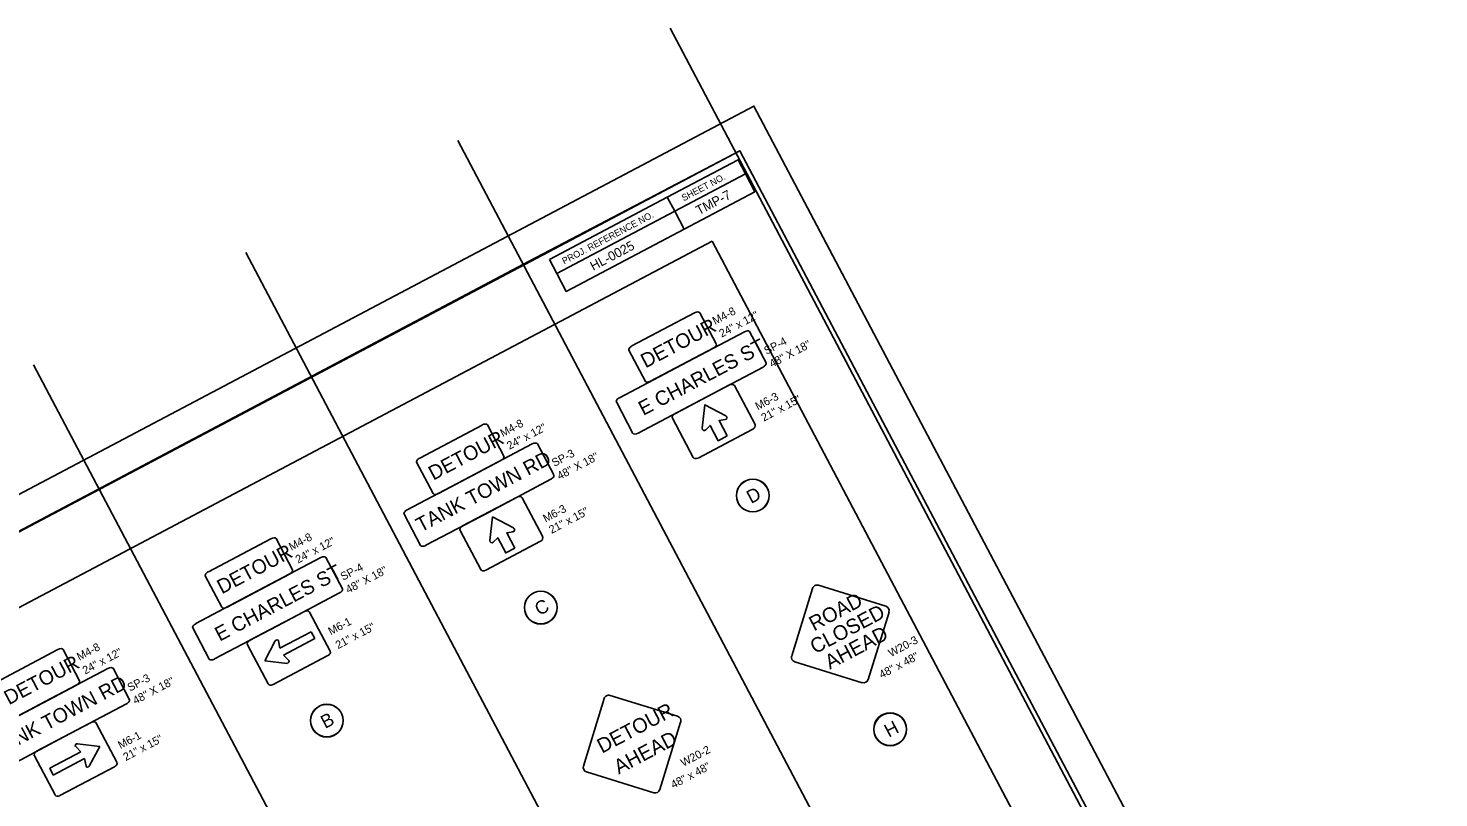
# Model space of a CAD drawing. Extents: x 1487176 to 2935813, y 497724 to 1002340.
# Drawn here: x 1488583 to 1489641, y 499179 to 499756 of the extents above; entities that cross this region are included whole.
import ezdxf

# ---------------------------------------------------------------- set-up
doc = ezdxf.new("R2010")
doc.units = 0
for name, color, linetype in [('DEV BORDER CELL', 7, 'Continuous'), ('Gray Area Fill Shapes', 7, 'Continuous'), ('GS M4-8 CELL', 7, 'Continuous'), ('Scratch_Level_0', 7, 'Continuous'), ('Scratch_Level_1', 7, 'Continuous'), ('Scratch_Level_3', 7, 'Continuous'), ('Sheet Plot Border Outside CELL', 7, 'Continuous'), ('WZ DETAHD CELL', 7, 'Continuous'), ('WZ OSDHWYEND CELL', 7, 'Continuous'), ('WZ OSDHWYL CELL', 7, 'Continuous'), ('WZ OSDHWYR CELL', 7, 'Continuous'), ('WZ OSDHWYS CELL', 7, 'Continuous'), ('WZ OSDR CELL', 7, 'Continuous'), ('WZ RCA CELL', 7, 'Continuous')]:
    doc.layers.add(name, color=color, linetype=linetype)

msp = doc.modelspace()

# ---------------------------------------------------------------- linework, layer by layer
at = {"layer": 'DEV BORDER CELL'}
msp.add_line((1489068, 499618.8), (1489121.1, 499646.8), dxfattribs=at)
for points in [[(1489116.9, 499664), (1487790.5, 498963.6), (1488280.8, 498035.1), (1489607.2, 498735.4)], [(1489068, 499618.8), (1489121.1, 499646.8), (1489115.5, 499657.4), (1489062.4, 499629.4)], [(1489068, 499618.8), (1489121.1, 499646.8), (1489128.1, 499633.5), (1489075, 499605.5)], [(1488974, 499582.7), (1489062.4, 499629.4), (1489068, 499618.8), (1488979.6, 499572.1)], [(1489068, 499618.8), (1488979.6, 499572.1), (1488986.6, 499558.8), (1489075, 499605.5)]]:
    msp.add_lwpolyline(points, close=True, dxfattribs=at)
at = {"layer": 'Gray Area Fill Shapes'}
for centre in [(1489126.5, 499405.8), (1488967.5, 499321.8), (1488807.1, 499237.1), (1489229.6, 499230.5)]:
    msp.add_circle(centre, 12.2, dxfattribs=at)
at = {"layer": 'GS M4-8 CELL'}
for p, q in [((1489073.3, 499503.8), (1489120.2, 499528.5)), ((1489134.2, 499502), (1489087.4, 499477.3)), ((1489087.4, 499477.3), (1489040.5, 499452.5)), ((1488914.2, 499419.7), (1488961, 499444.5)), ((1488975, 499418), (1488928.2, 499393.2)), ((1488928.2, 499393.2), (1488881.3, 499368.5)), ((1488755.6, 499334.5), (1488802.5, 499359.3)), ((1488816.5, 499332.8), (1488769.6, 499308)), ((1488769.6, 499308), (1488722.8, 499283.3)), ((1488595.9, 499251.4), (1488642.8, 499276.2)), ((1488656.8, 499249.6), (1488609.9, 499224.9)), ((1488609.9, 499224.9), (1488563, 499200.1))]:
    msp.add_line(p, q, dxfattribs=at)
for points in [[(1489124.1, 499528.6), (1489136.5, 499505.2)], [(1489026.5, 499479), (1489073.3, 499503.8)], [(1489036.6, 499452.4), (1489024.2, 499475.9)], [(1488965, 499444.6), (1488977.3, 499421.2)], [(1488867.3, 499395), (1488914.2, 499419.7)], [(1488877.4, 499368.4), (1488865, 499391.8)], [(1488806.4, 499359.4), (1488818.8, 499335.9)], [(1488708.7, 499309.8), (1488755.6, 499334.5)], [(1488718.8, 499283.2), (1488706.5, 499306.6)], [(1488646.7, 499276.3), (1488659.1, 499252.8)], [(1488549, 499226.7), (1488595.9, 499251.4)]]:
    msp.add_lwpolyline(points, dxfattribs=at)
for centre, major_axis, start_param, end_param in [((1489121, 499527), (3.1, 1.63), 0, 1.570796), ((1489133.4, 499503.6), (-3.1, -1.63), 1.570796, 3.141593), ((1489027.3, 499477.5), (-3.1, -1.63), 4.712162, 6.283185), ((1489039.7, 499454.1), (-3.1, -1.63), 0, 1.570796), ((1488961.9, 499442.9), (3.1, 1.63), 0, 1.570796), ((1488974.2, 499419.5), (-3.1, -1.63), 1.570796, 3.141593), ((1488868.1, 499393.5), (-3.1, -1.63), 4.712162, 6.283185), ((1488880.5, 499370), (-3.1, -1.63), 0, 1.570796), ((1488803.3, 499357.7), (3.1, 1.63), 0, 1.570796), ((1488815.7, 499334.3), (-3.1, -1.63), 1.570796, 3.141593), ((1488709.6, 499308.2), (-3.1, -1.63), 4.712162, 6.283185), ((1488721.9, 499284.8), (-3.1, -1.63), 0, 1.570796), ((1488643.6, 499274.6), (3.1, 1.63), 0, 1.570796), ((1488656, 499251.2), (-3.1, -1.63), 1.570796, 3.141593)]:
    msp.add_ellipse(centre, major_axis=major_axis, ratio=0.5, start_param=start_param, end_param=end_param, dxfattribs=at)
at = {"layer": 'Scratch_Level_0'}
msp.add_lwpolyline([(1489096.1, 499596.4), (1487858.1, 498942.7), (1488301.6, 498102.6), (1489078.8, 498513), (1489023.6, 498617.6), (1489484.4, 498860.9)], close=True, dxfattribs=at)
at = {"layer": 'Scratch_Level_1'}
for p, q in [((1489064.6, 499756), (1489604.7, 498733.1)), ((1488905.4, 499671.9), (1489445.5, 498649)), ((1488746.2, 499587.9), (1489286.3, 498565)), ((1488587.1, 499503.8), (1489127.2, 498481))]:
    msp.add_line(p, q, dxfattribs=at)
at = {"layer": 'Scratch_Level_3'}
msp.add_lwpolyline([(1487790.5, 498963.6), (1488958.9, 499581.5), (1489116.9, 499664), (1489607.2, 498735.4), (1488280.8, 498035.1)], close=True, dxfattribs=at)
at = {"layer": 'Sheet Plot Border Outside CELL'}
msp.add_lwpolyline([(1488148.3, 497936.8), (1489641, 498725), (1489127.4, 499697.7), (1487634.7, 498909.6)], close=True, dxfattribs=at)
at = {"layer": 'WZ DETAHD CELL'}
for points in [[(1488999.5, 499203.1), (1489015.1, 499253.7)], [(1489019.5, 499256), (1489070.1, 499240.4)], [(1489072.4, 499236), (1489056.8, 499185.4)], [(1489052.4, 499183.1), (1489001.8, 499198.7)]]:
    msp.add_lwpolyline(points, dxfattribs=at)
for centre, start, end in [((1489018.4, 499252.7), 72.8221, 162.8351), ((1489069.1, 499237), 342.8351, 72.8351), ((1489002.8, 499202), 162.8351, 252.8351), ((1489053.4, 499186.4), 252.8351, 342.8351)]:
    msp.add_arc(centre, 3.5, start, end, dxfattribs=at)
at = {"layer": 'WZ OSDHWYEND CELL'}
msp.add_circle((1489229.5, 499230.7), 12.3, dxfattribs=at)
at = {"layer": 'WZ OSDHWYL CELL'}
for p, q in [((1488769.8, 499308.1), (1488769.8, 499308.1)), ((1488795.3, 499303.7), (1488771.9, 499291.3)), ((1488798, 499298.6), (1488795.3, 499303.7)), ((1488768.3, 499296.9), (1488760.5, 499282)), ((1488771.9, 499291.3), (1488770.8, 499296.9)), ((1488774.6, 499286.2), (1488798, 499298.6)), ((1488778.6, 499282.1), (1488774.6, 499286.2)), ((1488760.5, 499282), (1488777.2, 499280))]:
    msp.add_line(p, q, dxfattribs=at)
for points in [[(1489035.9, 499517.9), (1489082.8, 499542.7)], [(1489086.7, 499542.8), (1489099.1, 499519.4)], [(1489096.8, 499516.2), (1489049.9, 499491.4)], [(1489046, 499491.3), (1489033.6, 499514.8)], [(1488876.7, 499433.9), (1488923.6, 499458.6)], [(1488927.5, 499458.7), (1488939.9, 499435.3)], [(1488886.8, 499407.3), (1488874.4, 499430.7)], [(1488937.6, 499432.1), (1488890.7, 499407.4)], [(1488718.2, 499348.7), (1488765, 499373.4)], [(1488769, 499373.5), (1488781.3, 499350.1)], [(1488779, 499346.9), (1488732.2, 499322.2)], [(1488728.3, 499322.1), (1488715.9, 499345.5)], [(1488749.3, 499297.3), (1488790.3, 499318.9)], [(1488794, 499318.4), (1488809.5, 499289.1)], [(1488763.1, 499264.6), (1488747.6, 499293.9)], [(1488807.8, 499285.8), (1488766.8, 499264.1)]]:
    msp.add_lwpolyline(points, dxfattribs=at)
for centre in [(1489126.5, 499405.8), (1488967.5, 499321.8)]:
    msp.add_circle(centre, 12.3, dxfattribs=at)
for centre, major_axis, ratio, start_param, end_param in [((1489083.6, 499541.1), (3.1, 1.63), 0.5, 0, 1.570796), ((1489036.7, 499516.4), (-3.1, -1.63), 0.5, 4.712162, 6.283185), ((1489096, 499517.7), (-3.1, -1.63), 0.5, 1.570796, 3.141593), ((1489049.1, 499493), (-3.1, -1.63), 0.5, 0, 1.570796), ((1488924.4, 499457.1), (3.1, 1.63), 0.5, 0, 1.570796), ((1488877.5, 499432.3), (-3.1, -1.63), 0.5, 4.712162, 6.283185), ((1488936.8, 499433.7), (-3.1, -1.63), 0.5, 1.570796, 3.141593), ((1488889.9, 499408.9), (-3.1, -1.63), 0.5, 0, 1.570796), ((1488765.9, 499371.9), (3.1, 1.63), 0.5, 0, 1.570796), ((1488719, 499347.1), (-3.1, -1.63), 0.5, 4.712162, 6.283185), ((1488778.2, 499348.5), (-3.1, -1.63), 0.5, 1.570796, 3.141593), ((1488731.4, 499323.7), (-3.1, -1.63), 0.5, 0, 1.570796), ((1488791.3, 499317), (2.71, 1.43), 0.714286, 0, 1.570796), ((1488750.3, 499295.3), (-2.71, -1.43), 0.714286, 4.712162, 6.283185), ((1488769.4, 499296.5), (-1.26, -0.67), 0.720018, 2.830616, 5.313575), ((1488806.8, 499287.7), (-2.71, -1.43), 0.714286, 1.570796, 3.141593), ((1488777.5, 499281.2), (-1.26, -0.67), 0.720018, 0.969609, 3.452568), ((1488765.8, 499266), (-2.71, -1.43), 0.714286, 0, 1.570796)]:
    msp.add_ellipse(centre, major_axis=major_axis, ratio=ratio, start_param=start_param, end_param=end_param, dxfattribs=at)
at = {"layer": 'WZ OSDHWYR CELL'}
for p, q in [((1488609.9, 499224.9), (1488609.9, 499224.9)), ((1488620, 499219.8), (1488636.7, 499217.8)), ((1488599.2, 499201.4), (1488622.6, 499213.7)), ((1488625.3, 499208.6), (1488601.9, 499196.3)), ((1488622.6, 499213.7), (1488618.7, 499217.8)), ((1488626.5, 499203), (1488625.3, 499208.6)), ((1488636.7, 499217.8), (1488628.9, 499202.9)), ((1488601.9, 499196.3), (1488599.2, 499201.4))]:
    msp.add_line(p, q, dxfattribs=at)
for points in [[(1488558.5, 499265.6), (1488605.3, 499290.3)], [(1488609.2, 499290.4), (1488621.6, 499267)], [(1488619.3, 499263.8), (1488572.5, 499239)], [(1488589.4, 499214.1), (1488630.4, 499235.7)], [(1488634.1, 499235.2), (1488649.6, 499205.9)], [(1488603.2, 499181.4), (1488587.7, 499210.7)], [(1488647.9, 499202.6), (1488606.9, 499180.9)]]:
    msp.add_lwpolyline(points, dxfattribs=at)
msp.add_circle((1488807.1, 499237.1), 12.3, dxfattribs=at)
for centre, major_axis, ratio, start_param, end_param in [((1488606.1, 499288.8), (3.1, 1.63), 0.5, 0, 1.570796), ((1488618.5, 499265.3), (-3.1, -1.63), 0.5, 1.570796, 3.141593), ((1488631.4, 499233.8), (2.71, 1.43), 0.714286, 0, 1.570796), ((1488619.7, 499218.7), (1.26, 0.67), 0.720018, 0.96961, 3.452569), ((1488590.4, 499212.1), (-2.71, -1.43), 0.714286, 4.712162, 6.283185), ((1488627.8, 499203.3), (1.26, 0.67), 0.720018, 2.830617, 5.313577), ((1488646.9, 499204.5), (-2.71, -1.43), 0.714286, 1.570796, 3.141593), ((1488605.9, 499182.8), (-2.71, -1.43), 0.714286, 0, 1.570796)]:
    msp.add_ellipse(centre, major_axis=major_axis, ratio=ratio, start_param=start_param, end_param=end_param, dxfattribs=at)
at = {"layer": 'WZ OSDHWYS CELL'}
for p, q in [((1489088.5, 499477.9), (1489088.5, 499477.9)), ((1488929.3, 499393.8), (1488929.3, 499393.8))]:
    msp.add_line(p, q, dxfattribs=at)
for points in [[(1489068, 499467), (1489109, 499488.7)], [(1489112.7, 499488.2), (1489128.2, 499458.9)], [(1489106.3, 499465.6), (1489090.6, 499473.8), (1489088.5, 499456.2)], [(1489106.3, 499465.6), (1489090.6, 499473.8), (1489088.5, 499456.2)], [(1489106.3, 499465.6), (1489090.6, 499473.8), (1489088.5, 499456.2)], [(1489081.7, 499434.4), (1489066.3, 499463.7)], [(1489107.2, 499450.5), (1489101.2, 499461.9), (1489105.9, 499462.7)], [(1489107.2, 499450.5), (1489101.2, 499461.9), (1489105.9, 499462.7)], [(1489107.2, 499450.5), (1489101.2, 499461.9), (1489105.9, 499462.7)], [(1489126.5, 499455.5), (1489085.5, 499433.9)], [(1489091.1, 499454.9), (1489094.5, 499458.3), (1489100.5, 499446.9), (1489107.2, 499450.5)], [(1489091.1, 499454.9), (1489094.5, 499458.3), (1489100.5, 499446.9), (1489107.2, 499450.5)], [(1489091.1, 499454.9), (1489094.5, 499458.3), (1489100.5, 499446.9), (1489107.2, 499450.5)], [(1488908.8, 499383), (1488949.8, 499404.6)], [(1488953.5, 499404.1), (1488969, 499374.8)], [(1488947.1, 499381.5), (1488931.4, 499389.8), (1488929.3, 499372.1)], [(1488947.1, 499381.5), (1488931.4, 499389.8), (1488929.3, 499372.1)], [(1488947.1, 499381.5), (1488931.4, 499389.8), (1488929.3, 499372.1)], [(1488922.5, 499350.3), (1488907.1, 499379.6)], [(1488948, 499366.4), (1488942, 499377.8), (1488946.7, 499378.6)], [(1488948, 499366.4), (1488942, 499377.8), (1488946.7, 499378.6)], [(1488948, 499366.4), (1488942, 499377.8), (1488946.7, 499378.6)], [(1488967.3, 499371.5), (1488926.3, 499349.8)], [(1488931.9, 499370.9), (1488935.3, 499374.2), (1488941.3, 499362.8), (1488948, 499366.4)], [(1488931.9, 499370.9), (1488935.3, 499374.2), (1488941.3, 499362.8), (1488948, 499366.4)], [(1488931.9, 499370.9), (1488935.3, 499374.2), (1488941.3, 499362.8), (1488948, 499366.4)]]:
    msp.add_lwpolyline(points, dxfattribs=at)
for centre, start, end in [((1489105.6, 499464.2), 280.2341, 62.2843), ((1489105.6, 499464.2), 280.2341, 62.2843), ((1489105.6, 499464.2), 280.2341, 62.2843), ((1489090.1, 499456), 173.3859, 315.436), ((1489090.1, 499456), 173.3859, 315.436), ((1489090.1, 499456), 173.3859, 315.436), ((1488946.4, 499380.1), 280.2341, 62.2843), ((1488946.4, 499380.1), 280.2341, 62.2843), ((1488946.4, 499380.1), 280.2341, 62.2843), ((1488930.8, 499371.9), 173.3859, 315.436), ((1488930.8, 499371.9), 173.3859, 315.436), ((1488930.8, 499371.9), 173.3859, 315.436)]:
    msp.add_arc(centre, 1.53, start, end, dxfattribs=at)
for centre, major_axis, start_param, end_param in [((1489110, 499486.7), (2.71, 1.43), 0, 1.570796), ((1489069, 499465.1), (-2.71, -1.43), 4.712162, 6.283185), ((1489125.5, 499457.5), (-2.71, -1.43), 1.570796, 3.141593), ((1489084.4, 499435.8), (-2.71, -1.43), 0, 1.570796), ((1488950.8, 499402.7), (2.71, 1.43), 0, 1.570796), ((1488909.8, 499381), (-2.71, -1.43), 4.712162, 6.283185), ((1488966.2, 499373.4), (-2.71, -1.43), 1.570796, 3.141593), ((1488925.2, 499351.7), (-2.71, -1.43), 0, 1.570796)]:
    msp.add_ellipse(centre, major_axis=major_axis, ratio=0.714286, start_param=start_param, end_param=end_param, dxfattribs=at)
at = {"layer": 'WZ RCA CELL'}
for points in [[(1489155.7, 499285.6), (1489171.3, 499336.2)], [(1489175.7, 499338.5), (1489226.3, 499322.9)], [(1489228.7, 499318.5), (1489213, 499267.9)], [(1489208.6, 499265.5), (1489158, 499281.2)]]:
    msp.add_lwpolyline(points, dxfattribs=at)
for centre, start, end in [((1489174.7, 499335.2), 72.8221, 162.8351), ((1489225.3, 499319.5), 342.8351, 72.8351), ((1489159, 499284.5), 162.8351, 252.8351), ((1489209.7, 499268.9), 252.8351, 342.8351)]:
    msp.add_arc(centre, 3.5, start, end, dxfattribs=at)

# ---------------------------------------------------------------- texts
at = {"layer": 'DEV BORDER CELL'}
for s, height, rotation, p in [('SHEET NO.', 5, 27.8356, (1489074.7, 499626.2)), ('TMP-7', 7, 27.8351, (1489086.1, 499615.8)), ('PROJ. REFERENCE NO.', 4.999, 27.8356, (1488985.1, 499578.9)), ('HL-0025', 7, 27.8351, (1489006.8, 499574.1))]:
    msp.add_text(s, height=height, rotation=rotation, dxfattribs=at).set_placement(p)
at = {"layer": 'GS M4-8 CELL'}
for s, height, p in [('E CHARLES ST', 10.83, (1489044.4, 499465.4)), ('SP-4', 6, (1489136.9, 499511.2)), ("48'' X 18''", 6, (1489140.9, 499501.5)), ('TANK TOWN RD', 10.83, (1488877.5, 499378)), ('SP-3', 6, (1488977.7, 499427.2)), ("48'' X 18''", 6, (1488981.7, 499417.4)), ('E CHARLES ST', 10.83, (1488726.7, 499296.2)), ('SP-4', 6, (1488819.2, 499341.9)), ("48'' X 18''", 6, (1488823.2, 499332.2)), ('SP-3', 6, (1488659.4, 499258.8)), ('TANK TOWN RD', 10.83, (1488559.2, 499209.7)), ("48'' X 18''", 6, (1488663.5, 499249.1))]:
    msp.add_text(s, height=height, rotation=27.8354, dxfattribs=at).set_placement(p)
at = {"layer": 'WZ DETAHD CELL'}
for s, height, p in [('DETOUR', 11, (1489013.4, 499212.3)), ('AHEAD', 11, (1489026, 499196.6)), ('W20-2', 6, (1489074.4, 499202.4)), ('48" x 48"', 6, (1489067, 499186))]:
    msp.add_text(s, height=height, rotation=27.8351, dxfattribs=at).set_placement(p)
at = {"layer": 'WZ OSDHWYL CELL'}
for s, height, p in [('M4-8', 6, (1489098.2, 499533.6)), ('DETOUR', 10.83, (1489046.1, 499501)), ('24" x 12"', 6, (1489103.2, 499524.1)), ('M4-8', 6, (1488939, 499449.5)), ('DETOUR', 10.83, (1488886.9, 499416.9)), ('24" x 12"', 6, (1488944, 499440)), ('M4-8', 6, (1488780.5, 499364.3)), ('DETOUR', 10.83, (1488728.3, 499331.7)), ('24" x 12"', 6, (1488785.5, 499354.8)), ('M6-1', 6, (1488810, 499301)), ('21" x 15"', 6, (1488815.5, 499290.6))]:
    msp.add_text(s, height=height, rotation=27.8351, dxfattribs=at).set_placement(p)
at = {"layer": 'WZ OSDHWYR CELL'}
for s, height, p in [('M4-8', 6, (1488621.5, 499281.9)), ('DETOUR', 10.83, (1488568.6, 499248.6)), ('24" x 12"', 6, (1488625.8, 499271.6)), ('M6-1', 6, (1488652.3, 499215.7)), ('21" x 15"', 6, (1488656.3, 499206.7))]:
    msp.add_text(s, height=height, rotation=27.8351, dxfattribs=at).set_placement(p)
at = {"layer": 'WZ OSDHWYS CELL'}
for s, p in [('M6-3', (1489130.3, 499469.6)), ('21" x 15"', (1489134.8, 499461.1)), ('M6-3', (1488971.1, 499385.5)), ('21" x 15"', (1488975.6, 499377))]:
    msp.add_text(s, height=6, rotation=27.8351, dxfattribs=at).set_placement(p)
at = {"layer": 'WZ OSDR CELL'}
for s, p in [('D', (1489125.2, 499399.4)), ('C', (1488966.3, 499315.5)), ('B', (1488805.8, 499230.8)), ('H', (1489228.5, 499224.2))]:
    msp.add_text(s, height=10, rotation=27.8351, dxfattribs=at).set_placement(p)
at = {"layer": 'WZ RCA CELL'}
for s, height, p in [('ROAD', 11, (1489172.4, 499304)), ('CLOSED', 11, (1489173.2, 499286.8)), ('AHEAD', 11, (1489184.3, 499275.2)), ('W20-3', 6, (1489230.1, 499284.6)), ('48" x 48"', 6, (1489223.2, 499268.5))]:
    msp.add_text(s, height=height, rotation=27.8351, dxfattribs=at).set_placement(p)

doc.saveas('drawing.dxf')
